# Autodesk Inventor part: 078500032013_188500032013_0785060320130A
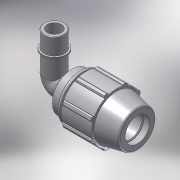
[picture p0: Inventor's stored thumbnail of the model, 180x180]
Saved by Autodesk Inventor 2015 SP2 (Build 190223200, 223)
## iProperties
Created: 2017-02
Part Number: 078500032013_188500032013_0785060320130A
Material: PVC-Piping
Description: PLASSON 90° ELBOW MALE ADAPTOR 32-1.1/4"
Document SubType Name: Modeling
Designer: KIM
Mass: 92.6774 g
Surface Area: 199.44 cm^2
Volume: 66.1981 cm^3
Density: 1.4 g/cm^3
Appearance: Smooth - White
Author: KIM
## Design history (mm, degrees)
derived "07850.ipt"
feature "Solid1::07850.ipt"
tag "TaggingFeature1"
body "Solid1"
other parameters: "d2" = 32, "d4" = 8.66667, "d5" = 26, "d7" = 64, "d9" = 14.85714, "d11" = 3.46667, "d13" = 120 deg, "d14" = 44.8, "d15" = 12 deg, "d16" = 55.68, "d18" = 1.6, "d19" = 35 deg, "d20" = 17.5 deg, "d21" = 59.52, "d23" = 0, "d25" = 360 deg, "d27" = 1.28, "d33" = 0.64, "d42" = 38.48, "d43" = 1.92, "d46" = 0.96, "d51" = 104, "d68" = 3.46667, "d72" = 58, "d73" = 41.91, "d74" = 22, "d75" = 48.1965, "d76" = 29.337, "d77" = 24.2, "d79" = 16.764, "d80" = 1.2573, "d83" = 0, "d84" = 0, "d91" = 48, "d93" = 67, "d94" = 41.91, "d95" = 29.337, "d96" = 10.4, "d97" = 50 deg, "d_" = 32, "E_" = 64, "A_" = 104, "l_" = 67, "l_2" = 22, "A_1" = 58, "R_" = 41.91
